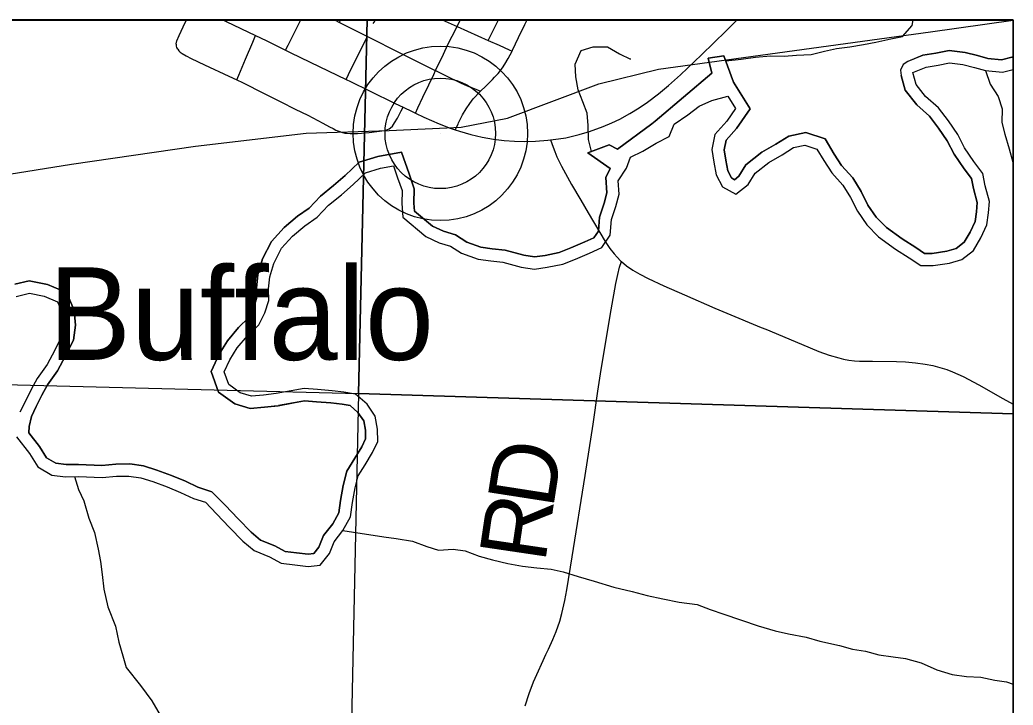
# Model space of a CAD drawing. Extents: x 0 to 34, y 0 to 22.
# Drawn here: x 7.584 to 8.431, y 20.789 to 21.373 of the extents above; entities that cross this region are included whole.
import ezdxf

# ---------------------------------------------------------------- set-up
doc = ezdxf.new("R2010")
doc.units = 0
for name, color, linetype in [('GM_X_Corporation', 7, 'Continuous'), ('GM_X_County_Road', 7, 'Continuous'), ('GM_X_County_Road_Text', 7, 'Continuous'), ('GM_X_Major_River', 7, 'Continuous'), ('GM_X_Minor_River', 7, 'Continuous'), ('GM_X_Rail_Line', 7, 'Continuous'), ('GM_X_State_Route', 7, 'Continuous'), ('GM_X_Township_Road', 7, 'Continuous'), ('GM_X_Unincorporated', 7, 'Continuous'), ('GM_X_Unincorporated_Location', 7, 'Continuous'), ('GM_X_Unincorporated_Text', 7, 'Continuous'), ('SH_Text', 7, 'Continuous')]:
    doc.layers.add(name, color=color, linetype=linetype)

msp = doc.modelspace()

# ---------------------------------------------------------------- linework, layer by layer
at = {"layer": 'GM_X_Corporation'}
for points in [[(4.78235, 18.12798), (4.7905, 18.36042), (4.80738, 19.54552), (4.81686, 20.04198), (4.81942, 20.1261), (5.11003, 20.11603), (6.05508, 20.08447), (6.49014, 20.07523), (6.72039, 20.06594), (7.3691, 20.05147), (7.39015, 20.05103), (7.81402, 20.04248), (8.43113, 20.02804), (8.43113, 21.3734), (1.63113, 21.3734)], [(4.05075, 18.14544), (4.78235, 18.12798), (4.7905, 18.36042), (4.80738, 19.54552), (4.81686, 20.04198), (4.81942, 20.1261), (5.11003, 20.11603), (6.05508, 20.08447), (6.49014, 20.07523), (6.72039, 20.06594), (7.3691, 20.05147), (7.39015, 20.05103), (7.81402, 20.04248), (8.43113, 20.02804), (8.43113, 21.3734), (2.79867, 21.3734)]]:
    msp.add_lwpolyline(points, dxfattribs=at)
for points in [[(7.88001, 21.3734), (6.86066, 21.3734), (6.85437, 21.08062), (7.87286, 21.05482)], [(8.43113, 21.03746), (8.43113, 21.3734), (7.88001, 21.3734), (7.87286, 21.05482)], [(7.87286, 21.05482), (7.85116, 20.0413), (6.83377, 20.06829), (6.85437, 21.08062)], [(8.43113, 20.02768), (8.43113, 21.03746), (7.87286, 21.05482), (7.85116, 20.0413)]]:
    msp.add_lwpolyline(points, close=True, dxfattribs=at)
at = {"layer": 'GM_X_County_Road'}
for points in [[(8.03659, 21.27097), (8.03874, 21.26493), (8.0401, 21.26107), (8.04193, 21.25656), (8.04592, 21.24871), (8.05456, 21.23298), (8.06229, 21.21953), (8.06852, 21.20879), (8.08313, 21.18428), (8.08715, 21.17843), (8.09069, 21.17391), (8.09337, 21.17087), (8.09609, 21.16798), (8.09703, 21.1672)], [(8.01499, 20.78825), (8.01844, 20.79889), (8.02213, 20.80878), (8.02476, 20.81509), (8.03018, 20.82697), (8.03258, 20.83201), (8.03472, 20.8365), (8.03864, 20.84491), (8.04143, 20.85179), (8.04443, 20.86058), (8.04625, 20.86716), (8.04868, 20.87807), (8.05042, 20.88723), (8.05511, 20.91542), (8.06594, 20.98481), (8.07278, 21.02841), (8.07702, 21.05668), (8.07985, 21.0751), (8.08827, 21.12598), (8.09214, 21.14864), (8.09388, 21.15627), (8.0955, 21.16243), (8.09703, 21.1672)], [(8.09703, 21.1672), (8.10126, 21.16367), (8.10684, 21.15988), (8.1127, 21.1565), (8.11985, 21.15283), (8.13332, 21.14649), (8.15094, 21.13875), (8.17657, 21.1276), (8.18687, 21.12327), (8.21613, 21.11112), (8.22014, 21.10945), (8.25048, 21.09664), (8.26541, 21.09058), (8.27414, 21.08746), (8.28245, 21.08511), (8.28644, 21.08408), (8.29096, 21.08323), (8.29585, 21.0827), (8.3001, 21.08237), (8.3112, 21.08214), (8.33172, 21.08203), (8.3392, 21.0817), (8.34792, 21.08095), (8.35598, 21.07983), (8.36273, 21.0785), (8.3706, 21.0764), (8.37469, 21.07506), (8.37944, 21.07323), (8.38855, 21.06908), (8.40177, 21.0621), (8.42237, 21.05052), (8.43113, 21.04554)]]:
    msp.add_lwpolyline(points, dxfattribs=at)
at = {"layer": 'GM_X_Major_River'}
for points in [[(7.80372, 21.04427), (7.79262, 21.043), (7.78026, 21.04196), (7.76724, 21.04599), (7.75339, 21.05592), (7.74693, 21.07355), (7.75384, 21.08828), (7.76087, 21.0997), (7.77035, 21.11107), (7.77923, 21.11945), (7.78323, 21.12734), (7.7858, 21.13561), (7.78572, 21.14441), (7.78691, 21.15615), (7.79076, 21.16943), (7.79854, 21.18448), (7.80928, 21.19634), (7.82069, 21.20592), (7.83072, 21.21288), (7.84019, 21.22293), (7.85147, 21.23208), (7.8613, 21.24064), (7.87341, 21.25212), (7.88913, 21.25694), (7.90946, 21.26067), (7.91583, 21.24207), (7.92032, 21.22936), (7.92001, 21.21696), (7.92051, 21.21014), (7.93585, 21.19738), (7.94537, 21.19305), (7.95551, 21.18991), (7.96524, 21.1838), (7.97716, 21.17942), (7.98683, 21.17819), (7.99781, 21.17708), (8.01363, 21.17262), (8.0228, 21.17118), (8.03188, 21.17253), (8.04394, 21.17508), (8.05395, 21.17901), (8.0658, 21.18397), (8.07348, 21.18736), (8.0774, 21.19327), (8.07831, 21.20513), (8.08231, 21.21711), (8.08469, 21.22574), (8.0837, 21.23885), (8.08741, 21.24661), (8.0684, 21.26006), (8.08648, 21.26669), (8.0937, 21.26297), (8.12293, 21.28469), (8.12593, 21.28687), (8.17403, 21.32784), (8.17089, 21.34069), (8.18448, 21.34273), (8.1926, 21.32026), (8.20674, 21.2974), (8.19503, 21.28064), (8.18639, 21.27083), (8.18475, 21.26245), (8.18606, 21.25379), (8.18773, 21.24455), (8.19092, 21.23852), (8.19352, 21.23707), (8.19723, 21.24006), (8.20322, 21.24962), (8.21684, 21.26041), (8.22861, 21.26725), (8.23983, 21.27432), (8.25417, 21.27725), (8.27075, 21.27189), (8.27838, 21.25891), (8.28469, 21.24927), (8.29432, 21.23867), (8.3016, 21.22689), (8.30726, 21.21544), (8.31437, 21.20513), (8.32304, 21.19627), (8.33652, 21.18652), (8.34818, 21.17915), (8.35552, 21.17416), (8.36215, 21.17423), (8.37469, 21.17606), (8.38263, 21.17843), (8.38931, 21.18369), (8.39441, 21.19227), (8.39872, 21.20144), (8.39987, 21.20976), (8.40041, 21.21754), (8.39723, 21.22948), (8.39562, 21.23806), (8.3893, 21.24644), (8.38075, 21.25885), (8.37498, 21.27015), (8.36744, 21.28109), (8.35979, 21.29135), (8.34885, 21.30099), (8.33892, 21.31354), (8.33563, 21.32582)], [(8.33563, 21.32582), (8.33892, 21.31354), (8.34885, 21.30099), (8.35979, 21.29135), (8.36744, 21.28109), (8.37498, 21.27015), (8.38075, 21.25885), (8.3893, 21.24644), (8.39562, 21.23806), (8.39723, 21.22948), (8.40041, 21.21754), (8.39987, 21.20976), (8.39872, 21.20144), (8.39441, 21.19227), (8.38931, 21.18369), (8.38263, 21.17843), (8.37469, 21.17606), (8.36215, 21.17423), (8.35552, 21.17416), (8.34818, 21.17915), (8.33652, 21.18652), (8.32304, 21.19627), (8.31437, 21.20513), (8.30726, 21.21544), (8.3016, 21.22689), (8.29432, 21.23867), (8.28469, 21.24927), (8.27838, 21.25891), (8.27075, 21.27189), (8.25417, 21.27725), (8.23983, 21.27432), (8.22861, 21.26725), (8.21684, 21.26041), (8.20322, 21.24962), (8.19723, 21.24006), (8.19352, 21.23707), (8.19092, 21.23852), (8.18773, 21.24455), (8.18606, 21.25379), (8.18475, 21.26245), (8.18639, 21.27083), (8.19503, 21.28064), (8.20674, 21.2974), (8.1926, 21.32026), (8.18448, 21.34273), (8.17089, 21.34069), (8.17403, 21.32784), (8.12593, 21.28687), (8.12293, 21.28469), (8.0937, 21.26297), (8.08648, 21.26669), (8.0684, 21.26006), (8.08741, 21.24661), (8.0837, 21.23885), (8.08469, 21.22574), (8.08231, 21.21711), (8.07831, 21.20513), (8.0774, 21.19327), (8.07348, 21.18736), (8.0658, 21.18397), (8.05395, 21.17901), (8.04394, 21.17508), (8.03188, 21.17253), (8.0228, 21.17118), (8.01363, 21.17262), (7.99781, 21.17708), (7.98683, 21.17819), (7.97716, 21.17942), (7.96524, 21.1838), (7.95551, 21.18991), (7.94537, 21.19305), (7.93585, 21.19738), (7.92051, 21.21014), (7.92001, 21.21696), (7.92032, 21.22936), (7.91583, 21.24207), (7.90946, 21.26067), (7.88913, 21.25694), (7.87341, 21.25212), (7.8613, 21.24064), (7.85147, 21.23208), (7.84019, 21.22293), (7.83072, 21.21288), (7.82069, 21.20592), (7.80928, 21.19634), (7.79854, 21.18448), (7.79076, 21.16943), (7.78691, 21.15615), (7.78572, 21.14441), (7.7858, 21.13561), (7.78323, 21.12734), (7.77923, 21.11945), (7.77035, 21.11107), (7.76087, 21.0997), (7.75384, 21.08828), (7.74693, 21.07355), (7.75339, 21.05592), (7.76724, 21.04599), (7.78026, 21.04196), (7.79262, 21.043), (7.80409, 21.04431)], [(8.43113, 21.34165), (8.43008, 21.34146), (8.4213, 21.33941), (8.40948, 21.34053), (8.4008, 21.34287), (8.39024, 21.3456), (8.37654, 21.34729), (8.36529, 21.345), (8.35411, 21.34322), (8.34134, 21.33794)], [(8.34169, 21.33809), (8.35411, 21.34322), (8.36529, 21.345), (8.37654, 21.34729), (8.39024, 21.3456), (8.4008, 21.34287), (8.40948, 21.34053), (8.4213, 21.33941), (8.43008, 21.34146), (8.43113, 21.34165)], [(8.34134, 21.33794), (8.33738, 21.33534), (8.33499, 21.33057), (8.33563, 21.32582)], [(8.34565, 21.3285), (8.35695, 21.33317), (8.36714, 21.33479), (8.37695, 21.33679), (8.3883, 21.33539), (8.39815, 21.33284), (8.40763, 21.33029), (8.422, 21.32892), (8.43113, 21.33105)], [(7.80255, 21.05458), (7.79159, 21.05333), (7.7814, 21.05246), (7.77192, 21.05539), (7.76203, 21.06249), (7.75816, 21.07306), (7.76298, 21.08334), (7.76932, 21.09363), (7.77792, 21.10395), (7.78767, 21.11315), (7.79287, 21.12343), (7.79618, 21.13407), (7.7961, 21.14393), (7.79714, 21.15417), (7.80044, 21.16557), (7.80714, 21.17852), (7.8165, 21.18885), (7.827, 21.19767), (7.83752, 21.20498), (7.84726, 21.21531), (7.85815, 21.22414), (7.86828, 21.23296), (7.87878, 21.24292), (7.89159, 21.24684), (7.90254, 21.24885), (7.90603, 21.23866), (7.90991, 21.22771), (7.90962, 21.21672), (7.91048, 21.20498), (7.93028, 21.18852), (7.94167, 21.18333), (7.95115, 21.1804), (7.96065, 21.17444), (7.97468, 21.16928), (7.98566, 21.16788), (7.99587, 21.16685), (8.01141, 21.16247), (8.02277, 21.16069), (8.03371, 21.16232), (8.04692, 21.16511), (8.05784, 21.16939), (8.0699, 21.17444), (8.08044, 21.1791), (8.08753, 21.18979), (8.08855, 21.20306), (8.09223, 21.21408), (8.09516, 21.22472), (8.09431, 21.23608), (8.1014, 21.24676), (8.10472, 21.25627), (8.11526, 21.2613), (8.12654, 21.26824), (8.13783, 21.27404), (8.1419, 21.28432), (8.15355, 21.29239), (8.16331, 21.29969), (8.17423, 21.30473), (8.18781, 21.30829), (8.19433, 21.29775), (8.18686, 21.28706), (8.17675, 21.27559), (8.17422, 21.26268), (8.17583, 21.25208), (8.17781, 21.24112), (8.18319, 21.23094), (8.19459, 21.22462), (8.2051, 21.23307), (8.21106, 21.2426), (8.2227, 21.25182), (8.23398, 21.25838), (8.24376, 21.26454), (8.25357, 21.26654), (8.26381, 21.26324), (8.26956, 21.25344), (8.27646, 21.24291), (8.286, 21.2324), (8.29252, 21.22186), (8.29829, 21.21017), (8.30633, 21.19851), (8.31625, 21.18839), (8.33071, 21.17793), (8.34249, 21.17047), (8.35238, 21.16376), (8.36296, 21.16387), (8.37693, 21.16591), (8.38749, 21.16905), (8.39725, 21.17673), (8.40358, 21.1874), (8.40878, 21.19845), (8.4102, 21.20869), (8.41087, 21.21855), (8.40735, 21.23177), (8.40537, 21.24236), (8.39772, 21.25251), (8.38968, 21.26417), (8.38391, 21.27548), (8.37587, 21.28714), (8.36746, 21.29842), (8.35641, 21.30815), (8.34838, 21.3183), (8.34565, 21.3285)], [(7.57955, 21.14791), (7.59177, 21.1509), (7.60756, 21.14772), (7.62374, 21.14088), (7.63031, 21.12571), (7.6314, 21.113), (7.62956, 21.10028), (7.62283, 21.08691), (7.61612, 21.07397), (7.60746, 21.06204), (7.60268, 21.05331), (7.59793, 21.04355), (7.59369, 21.0352), (7.59194, 21.02664), (7.59157, 21.02104), (7.60052, 21.0095), (7.60674, 20.99986), (7.61455, 20.99517), (7.62341, 20.99412), (7.63399, 20.99423), (7.65392, 20.99333), (7.66572, 20.99456), (7.67756, 20.99469), (7.68944, 20.99305), (7.70072, 20.98941), (7.71328, 20.98483), (7.7251, 20.97984), (7.7357, 20.97485), (7.74774, 20.97096), (7.75912, 20.95933), (7.77017, 20.94771), (7.78126, 20.93645), (7.78911, 20.92966), (7.80141, 20.92487), (7.81012, 20.91995), (7.81981, 20.9188), (7.82992, 20.91755), (7.83462, 20.91813), (7.83892, 20.92357), (7.84299, 20.93344), (7.85079, 20.94341), (7.85584, 20.95283), (7.85738, 20.96331), (7.85962, 20.97634), (7.86267, 20.98857), (7.86949, 20.99946), (7.87549, 21.00922), (7.8787, 21.01607), (7.87863, 21.02344), (7.8772, 21.03137), (7.87229, 21.0386), (7.86556, 21.04445), (7.85892, 21.04566), (7.84922, 21.04664), (7.83679, 21.04764), (7.8268, 21.04854), (7.81727, 21.04679), (7.80446, 21.04438)], [(7.80409, 21.04431), (7.81727, 21.04679), (7.8268, 21.04854), (7.83679, 21.04764), (7.84922, 21.04664), (7.85892, 21.04566), (7.86556, 21.04445), (7.87229, 21.0386), (7.8772, 21.03137), (7.87863, 21.02344), (7.8787, 21.01607), (7.87549, 21.00922), (7.86949, 20.99946), (7.86267, 20.98857), (7.85962, 20.97634), (7.85738, 20.96331), (7.85584, 20.95283), (7.85079, 20.94341), (7.84299, 20.93344), (7.83892, 20.92357), (7.83462, 20.91813), (7.82992, 20.91755), (7.81981, 20.9188), (7.81012, 20.91995), (7.80141, 20.92487), (7.78911, 20.92966), (7.78126, 20.93645), (7.77017, 20.94771), (7.75912, 20.95933), (7.74774, 20.97096), (7.7357, 20.97485), (7.7251, 20.97984), (7.71328, 20.98483), (7.70072, 20.98941), (7.68944, 20.99305), (7.67756, 20.99469), (7.66572, 20.99456), (7.65392, 20.99333), (7.63399, 20.99423), (7.62341, 20.99412), (7.61455, 20.99517), (7.60674, 20.99986), (7.60052, 21.0095), (7.59157, 21.02104), (7.59194, 21.02664), (7.59369, 21.0352), (7.59793, 21.04355), (7.60268, 21.05331), (7.60746, 21.06204), (7.61612, 21.07397), (7.62283, 21.08691), (7.62956, 21.10028), (7.6314, 21.113), (7.63031, 21.12571), (7.62374, 21.14088), (7.60756, 21.14772), (7.59177, 21.1509), (7.57955, 21.14791)], [(7.58068, 21.1375), (7.59199, 21.14028), (7.60449, 21.13775), (7.61587, 21.13295), (7.62012, 21.12314), (7.62096, 21.1133), (7.61953, 21.10343), (7.61359, 21.09163), (7.60727, 21.07944), (7.59868, 21.0676), (7.59347, 21.05807), (7.58864, 21.04818), (7.58381, 21.03865)], [(7.58097, 21.01778), (7.59205, 21.0035), (7.59934, 20.99221), (7.61111, 20.98514), (7.62284, 20.98374), (7.63381, 20.98386), (7.65423, 20.98294), (7.66631, 20.9842), (7.6769, 20.98431), (7.68712, 20.9829), (7.69735, 20.9796), (7.70949, 20.97518), (7.72087, 20.97037), (7.73188, 20.96518), (7.74211, 20.96188), (7.75165, 20.95213), (7.76271, 20.9405), (7.77416, 20.92887), (7.78368, 20.92064), (7.79695, 20.91547), (7.80683, 20.90989), (7.81856, 20.9085), (7.82991, 20.90711), (7.84011, 20.90835), (7.84796, 20.91828), (7.85204, 20.92817), (7.85951, 20.93772), (7.86584, 20.94953), (7.86762, 20.96168), (7.86978, 20.9742), (7.87234, 20.98446), (7.8783, 20.99399), (7.88464, 21.00429), (7.88909, 21.01381), (7.889, 21.02441), (7.88701, 21.03538), (7.88012, 21.04554), (7.87022, 21.05415), (7.86037, 21.05594), (7.85016, 21.05697), (7.83767, 21.05798), (7.82632, 21.05899), (7.81538, 21.05699), (7.80255, 21.05458)]]:
    msp.add_lwpolyline(points, dxfattribs=at)
at = {"layer": 'GM_X_Minor_River'}
for points in [[(8.18607, 21.33834), (8.19925, 21.33985), (8.21134, 21.3415), (8.22418, 21.34277), (8.2359, 21.34251), (8.24647, 21.34338), (8.25894, 21.34389), (8.27026, 21.34666), (8.28045, 21.34904), (8.29178, 21.35029), (8.30348, 21.35231), (8.31405, 21.35432), (8.32687, 21.3571), (8.33668, 21.3591), (8.34492, 21.36866), (8.34575, 21.3734)], [(8.0716, 21.26123), (8.06905, 21.27143), (8.06857, 21.28317), (8.06772, 21.29377), (8.06423, 21.30359), (8.05999, 21.31377), (8.058, 21.32474), (8.05753, 21.33572), (8.06272, 21.34714), (8.0729, 21.35028), (8.085, 21.3504), (8.09525, 21.34445), (8.10474, 21.34), (8.10474, 21.34038)], [(8.40763, 21.33029), (8.41151, 21.31858), (8.41841, 21.30804), (8.4219, 21.29747), (8.42162, 21.28572), (8.42398, 21.2759), (8.42787, 21.26343), (8.43099, 21.2521), (8.43113, 21.25179)], [(7.6304, 20.98382), (7.6339, 20.97287), (7.63852, 20.96307), (7.64281, 20.94834), (7.64745, 20.93626), (7.6506, 20.9219), (7.65259, 20.91131), (7.65419, 20.90034), (7.65544, 20.88785), (7.65897, 20.87273), (7.66554, 20.85613), (7.6683, 20.84252), (7.67181, 20.83081), (7.67454, 20.82099), (7.68677, 20.80559), (7.69634, 20.79243), (7.70362, 20.78038)], [(7.85951, 20.93772), (7.89434, 20.9324), (7.90493, 20.931), (7.91894, 20.92887), (7.93108, 20.92407), (7.94093, 20.92115), (7.9534, 20.92203), (7.96362, 20.92063), (7.97576, 20.91583), (7.98712, 20.91291), (8, 20.90964), (8.0125, 20.9075), (8.02498, 20.90611), (8.03709, 20.90472), (8.04732, 20.90256), (8.06021, 20.89853), (8.07385, 20.8945), (8.09053, 20.88937), (8.10606, 20.88574), (8.11894, 20.88247), (8.13219, 20.87958), (8.14621, 20.87669), (8.16173, 20.87458), (8.17272, 20.87053), (8.18448, 20.86648), (8.21367, 20.85656), (8.22808, 20.85216), (8.23944, 20.84963), (8.25458, 20.84676), (8.26633, 20.84347), (8.28299, 20.83986), (8.29399, 20.83656), (8.30534, 20.83479), (8.31671, 20.83188), (8.32882, 20.83011), (8.33942, 20.82871), (8.35268, 20.82505), (8.36596, 20.81913), (8.37923, 20.8151), (8.39134, 20.81334), (8.40344, 20.8127), (8.41556, 20.81018), (8.4254, 20.80877), (8.43113, 20.80677)]]:
    msp.add_lwpolyline(points, dxfattribs=at)
at = {"layer": 'GM_X_Rail_Line'}
msp.add_lwpolyline([(6.56447, 20.9858), (7.11368, 21.15576), (7.204, 21.17937), (7.29432, 21.19682), (7.6279, 21.25018), (7.73362, 21.26557), (7.82805, 21.27686), (7.89887, 21.27891), (7.96045, 21.28198), (7.99972, 21.28944), (8.07763, 21.31893), (8.12868, 21.33141), (8.36075, 21.36306), (8.43113, 21.37303)], dxfattribs=at)
at = {"layer": 'GM_X_State_Route'}
for points in [[(7.75715, 21.3734), (7.75986, 21.37209), (7.78498, 21.35998), (7.79384, 21.35571), (7.81046, 21.3476), (7.81505, 21.34536), (7.83909, 21.33371), (7.86215, 21.32252), (7.86592, 21.32069), (7.88214, 21.31284), (7.90389, 21.30218), (7.91077, 21.2989), (7.91862, 21.29515)], [(7.91862, 21.29515), (7.92124, 21.29391), (7.92855, 21.29042), (7.94161, 21.28472), (7.95083, 21.28111), (7.95529, 21.2796), (7.95903, 21.27833), (7.96855, 21.27566), (7.97819, 21.27344), (7.98793, 21.27169), (7.99712, 21.27051), (8.00575, 21.26985), (8.01439, 21.26962), (8.02366, 21.26985), (8.03416, 21.27066), (8.03659, 21.27097), (8.04338, 21.27185), (8.04948, 21.2729), (8.06092, 21.27558), (8.06985, 21.27813), (8.08142, 21.28247), (8.08884, 21.28557), (8.09554, 21.28874), (8.10425, 21.29342), (8.11218, 21.29822), (8.11935, 21.30307), (8.1287, 21.31018), (8.13727, 21.3173), (8.14742, 21.3264), (8.16531, 21.34362), (8.18625, 21.36397), (8.19583, 21.3734)]]:
    msp.add_lwpolyline(points, dxfattribs=at)
at = {"layer": 'GM_X_Township_Road'}
for p, q in [((7.75986, 21.37209), (7.76046, 21.3734)), ((7.85218, 21.3734), (7.85646, 21.37124)), ((7.85646, 21.37124), (7.85736, 21.3734)), ((7.85646, 21.37124), (7.88033, 21.35921)), ((7.94415, 21.3734), (7.95678, 21.36774)), ((7.95678, 21.36774), (7.98348, 21.3558))]:
    msp.add_line(p, q, dxfattribs=at)
for points in [[(7.71859, 21.3484), (7.71789, 21.34969), (7.71749, 21.35104), (7.71736, 21.35216), (7.71735, 21.35309), (7.71788, 21.3555), (7.7197, 21.36016), (7.72312, 21.36758), (7.72599, 21.3734)], [(7.81046, 21.3476), (7.81266, 21.35184), (7.82055, 21.36707), (7.82354, 21.3734)], [(7.88538, 21.3703), (7.8861, 21.37133), (7.88716, 21.3734)], [(7.92124, 21.29391), (7.92337, 21.29842), (7.92763, 21.30747), (7.93269, 21.318), (7.93691, 21.32683), (7.93846, 21.33008), (7.94511, 21.34402), (7.94905, 21.35237), (7.95259, 21.35957), (7.95678, 21.36774)], [(7.95678, 21.36774), (7.95783, 21.3698), (7.95967, 21.3734)], [(7.98348, 21.3558), (7.98489, 21.35865), (7.99219, 21.3734)], [(8.00371, 21.34671), (8.00421, 21.34768), (8.00926, 21.35834), (8.0146, 21.36951), (8.01669, 21.3734)], [(7.76894, 21.32221), (7.77064, 21.32619), (7.77642, 21.33978), (7.78264, 21.35445), (7.78498, 21.35998)], [(7.86215, 21.32252), (7.86432, 21.3269), (7.87936, 21.35726), (7.88033, 21.35921)], [(7.88033, 21.35921), (7.90861, 21.34496), (7.93747, 21.33056), (7.93846, 21.33008)], [(7.98348, 21.3558), (7.99266, 21.35169), (8.00112, 21.34788), (8.00371, 21.34671)], [(7.71859, 21.3484), (7.71949, 21.34706), (7.7206, 21.34587), (7.72235, 21.3446), (7.7257, 21.34272), (7.73007, 21.34038), (7.74127, 21.33504), (7.76213, 21.32539), (7.76894, 21.32221)], [(7.9768, 21.31245), (7.98142, 21.31693), (7.98404, 21.31953), (7.98709, 21.3226), (7.98881, 21.32438), (7.99174, 21.3276), (7.99559, 21.33252), (7.99769, 21.33564), (8.00054, 21.34048), (8.00371, 21.34671)], [(7.93846, 21.33008), (7.94752, 21.32573), (7.95985, 21.31967), (7.96553, 21.31722), (7.97012, 21.31536), (7.97288, 21.31416), (7.9768, 21.31245)], [(7.76894, 21.32221), (7.77393, 21.31987), (7.79216, 21.31053), (7.8066, 21.30335), (7.81882, 21.29726), (7.8294, 21.29204), (7.84244, 21.28515), (7.84801, 21.28223), (7.85104, 21.28061), (7.85346, 21.27945), (7.85598, 21.27838), (7.85811, 21.27755)], [(7.95529, 21.2796), (7.95763, 21.28455), (7.95816, 21.28567), (7.96143, 21.2923), (7.96451, 21.2976), (7.96759, 21.30215), (7.97068, 21.30594), (7.9768, 21.31245)], [(7.85811, 21.27755), (7.86107, 21.27679), (7.8625, 21.27666), (7.86561, 21.27645), (7.86863, 21.27652), (7.87186, 21.27659), (7.88185, 21.27732), (7.89053, 21.27847), (7.89505, 21.2791), (7.8964, 21.27942), (7.89752, 21.27981), (7.89895, 21.28045), (7.90006, 21.28117), (7.90165, 21.28284), (7.90357, 21.28554), (7.90597, 21.28945), (7.90922, 21.29584), (7.91077, 21.2989)]]:
    msp.add_lwpolyline(points, dxfattribs=at)
at = {"layer": 'GM_X_Unincorporated'}
for radius in [0.0744, 0.04716]:
    msp.add_circle((7.94253, 21.27658), radius, dxfattribs=at)
at = {"layer": 'GM_X_Unincorporated_Location'}
msp.add_line((7.94253, 21.27658), (7.94253, 21.27658), dxfattribs=at)
at = {"layer": 'SH_Text'}
for p, q in [((1.63113, 21.3734), (8.43113, 21.37303)), ((8.43113, 21.37303), (8.43113, 14.5734))]:
    msp.add_line(p, q, dxfattribs=at)

# ---------------------------------------------------------------- texts
at = {"layer": 'GM_X_County_Road_Text'}
for s, rotation, p in [('D', 81.14194, (8.03863, 20.95555)), ('R', 81.58231, (8.03181, 20.9095))]:
    msp.add_text(s, height=0.05682, rotation=rotation, dxfattribs=at).set_placement(p)
at = {"layer": 'GM_X_Unincorporated_Text'}
msp.add_text('Buffalo', height=0.078977, rotation=0.00001, dxfattribs=at).set_placement((7.60826, 21.08337))

doc.saveas('drawing.dxf')
